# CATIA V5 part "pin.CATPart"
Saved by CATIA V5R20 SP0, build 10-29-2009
Part number: pin
Bounding box of the stored display mesh (mm): x -25 to 184.334, y -300 to 10, z 335 to 528.094
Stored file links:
  E:\Ehsan\Amoozesh\CATIA\CATIA Course\Basic\Exercises\Assembly\2\pin.CATPart
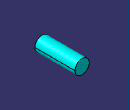
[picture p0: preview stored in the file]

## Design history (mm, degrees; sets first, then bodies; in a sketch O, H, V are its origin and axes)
Body1 (main body)
  Plane1: stored without definition
  DatumSurface1
  DatumCurve1
  DatumCurve2
  DatumSurface2
  DatumSurface3
  Sketch1 on Plane1, origin (0, -50, 0), H (-1, 0, 0), V (0, 0, 1)
    circle A1 centre (-147.3338, 491.0935) radius 37
    reference projected arc E1 centre (-424.937, 360) radius 270 from (-220.4005, 183.7478) to (-220.4005, 536.2522) ccw from edge of DatumCurve1
    reference projected arc E2 centre (-424.937, 360) radius 344 from (-167.9615, 131.3089) to (-167.9615, 588.6911) ccw from edge of DatumCurve2
    tangency: A1 E1, A1 E2
  Pad1: profile Sketch1, direction (0, 1, 0), up to face of DatumSurface3, opposite side length 150
  DatumSurface4
  Plane2: stored without definition
  DatumCurve3
  Sketch2 on face of DatumSurface4, origin (0, -300, 0), H (-1, 0, 0), V (0, 0, 1)
    circle A1 centre (0, 360) radius 25
    point P2 (0, 385)
    reference projected circle E1 centre (0, 360) radius 25 from edge of DatumCurve3
    coincidence: A1 P2, P2 V, A1 E1
  Pad2: profile Sketch2, direction (0, 1, 0), length 160
  DatumCurve4
  Sketch3 on start face of Pad1, origin (0, -200, 0), H (1, 0, 0), V (0, 0, 1)
    line L1 (136.0971, 499.8349) -> (154.7096, 478.9166)
    line L2 (154.7096, 478.9166) -> (20.753, 359.7259)
    line L3 (20.753, 359.7259) -> (2.1405, 380.6441)
    line L4 (2.1405, 380.6441) -> (136.0971, 499.8349)
    construction line L5 (147.3338, 491.0935) -> (0, 360)
    point P5 (0, 360)
    point P6 (147.3338, 491.0935)
    reference projected circle E1 centre (0, 360) radius 25 from edge of DatumCurve4
    reference projected circle E2 centre (147.3338, 491.0935) radius 37 from edge [start face of Pad1 | face of Pad1 from Sketch1.A1]
    distance L4 L2 = 28
    parallelism: L1 L3
    perpendicularity: L1 L2
    coincidence: P5 V
    concentricity: P5 E1, P6 E2
    symmetry: L2 L4 L5
  Pad3: profile Sketch3, direction (0, 1, 0), length 56, opposite side length -7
